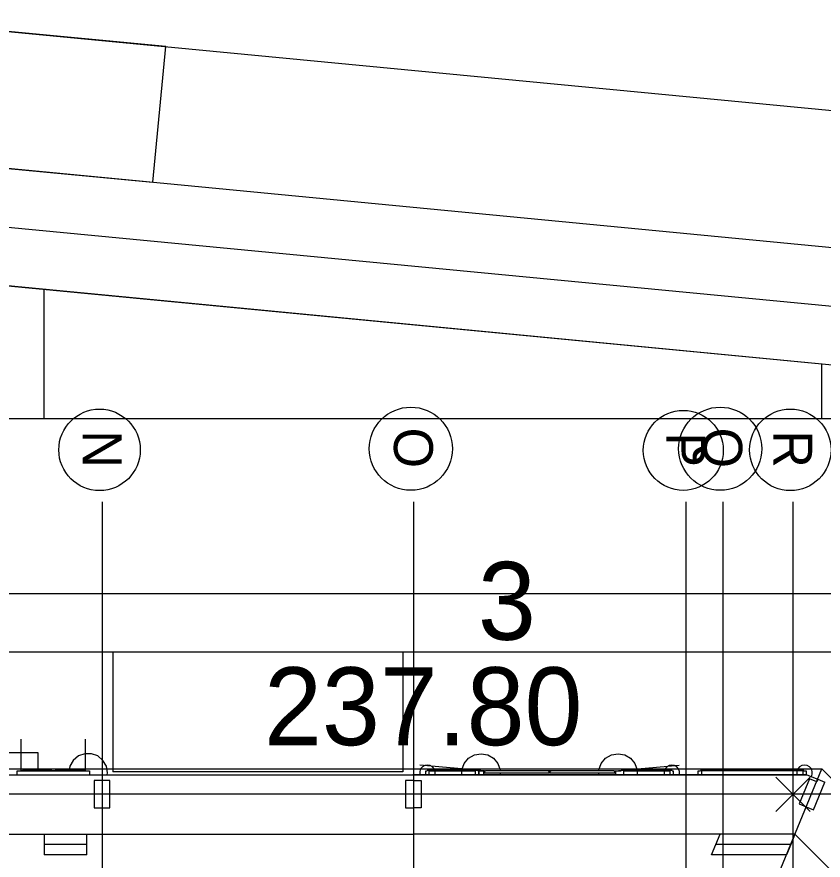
# Model space of a CAD drawing. Extents: x -264165 to -263575, y -1242333 to -1242036.
# Drawn here: x -263829.66 to -263808.94, y -1242089.65 to -1242067.99 of the extents above; entities that cross this region are included whole.
import ezdxf

# ---------------------------------------------------------------- set-up
doc = ezdxf.new("R2010")
doc.units = 0
for name, color, linetype in [('KFA_BODY_VYTYCOVAK', 7, 'Continuous'), ('KFA_HESCON_OSI_STAVBY', 7, 'Continuous'), ('KFA_SITUACIA_DRS_VYTYCOVAK_SEDA', 7, 'Continuous')]:
    doc.layers.add(name, color=color, linetype=linetype)

msp = doc.modelspace()

# ---------------------------------------------------------------- linework, layer by layer
at = {"layer": 'KFA_BODY_VYTYCOVAK'}
for p, q in [((-263810.152, -1242088.402), (-263809.268, -1242087.518)), ((-263809.268, -1242088.402), (-263810.152, -1242087.518))]:
    msp.add_line(p, q, dxfattribs=at)
at = {"layer": 'KFA_HESCON_OSI_STAVBY'}
for p, q in [((-263827.468, -1242080.447), (-263827.468, -1242080.447)), ((-263827.468, -1242080.447), (-263827.468, -1242248.737)), ((-263819.468, -1242080.447), (-263819.468, -1242080.447)), ((-263819.468, -1242080.447), (-263819.468, -1242248.737)), ((-263812.468, -1242080.447), (-263812.468, -1242080.447)), ((-263812.468, -1242080.447), (-263812.468, -1242248.737)), ((-263811.518, -1242080.447), (-263811.518, -1242080.447)), ((-263811.518, -1242080.447), (-263811.518, -1242248.737)), ((-263809.718, -1242080.447), (-263809.718, -1242080.447)), ((-263809.718, -1242080.447), (-263809.718, -1242248.737)), ((-263818.92, -1242111.335), (-263808.968, -1242087.307)), ((-263787.486, -1242087.957), (-263921.823, -1242087.957))]:
    msp.add_line(p, q, dxfattribs=at)
for centre, radius in [((-263827.533, -1242079.111), 1.047), ((-263819.533, -1242079.082), 1.068), ((-263812.533, -1242079.124), 1.027), ((-263811.583, -1242079.082), 1.068), ((-263809.783, -1242079.111), 1.047)]:
    msp.add_circle(centre, radius, dxfattribs=at)
at = {"layer": 'KFA_SITUACIA_DRS_VYTYCOVAK_SEDA'}
for p, q in [((-263765.318, -1242074.565), (-263863.949, -1242065.106)), ((-263825.827, -1242068.753), (-263832.746, -1242068.099)), ((-263765.364, -1242078.076), (-263864.283, -1242068.59)), ((-263826.161, -1242072.237), (-263825.827, -1242068.753)), ((-263766.58, -1242079.467), (-263864.426, -1242070.084)), ((-263765.366, -1242081.09), (-263864.57, -1242071.577)), ((-263766.58, -1242080.973), (-263864.546, -1242071.579)), ((-263833.106, -1242071.58), (-263826.161, -1242072.237)), ((-263828.968, -1242074.991), (-263828.968, -1242078.308)), ((-263808.968, -1242076.909), (-263828.968, -1242074.991)), ((-263808.968, -1242076.909), (-263828.968, -1242074.991)), ((-263828.968, -1242074.991), (-263828.968, -1242078.308)), ((-263808.968, -1242078.308), (-263808.968, -1242076.909)), ((-263808.968, -1242078.308), (-263808.968, -1242076.909)), ((-263918.093, -1242078.308), (-263807.725, -1242078.308)), ((-263828.968, -1242078.308), (-263808.968, -1242078.308)), ((-263828.968, -1242078.308), (-263823.968, -1242078.308)), ((-263823.968, -1242078.308), (-263808.968, -1242078.308)), ((-263808.225, -1242082.808), (-263916.593, -1242082.808)), ((-263807.725, -1242084.308), (-263851.968, -1242084.308)), ((-263827.188, -1242084.307), (-263827.188, -1242087.377)), ((-263827.188, -1242084.307), (-263827.188, -1242087.377)), ((-263819.738, -1242084.307), (-263827.188, -1242084.307)), ((-263819.738, -1242084.307), (-263827.188, -1242084.307)), ((-263819.738, -1242084.307), (-263819.738, -1242087.377)), ((-263819.738, -1242084.307), (-263819.738, -1242087.377)), ((-263829.543, -1242087.357), (-263829.543, -1242086.542)), ((-263829.543, -1242087.357), (-263829.543, -1242086.542)), ((-263827.893, -1242087.357), (-263827.893, -1242086.542)), ((-263827.893, -1242087.357), (-263827.893, -1242086.542)), ((-263829.108, -1242086.896), (-263832.828, -1242086.896)), ((-263829.108, -1242086.896), (-263832.828, -1242086.896)), ((-263829.108, -1242087.347), (-263829.108, -1242086.896)), ((-263829.108, -1242087.347), (-263829.108, -1242086.896)), ((-263828.078, -1242086.974), (-263828.211, -1242087.086)), ((-263828.078, -1242086.974), (-263828.211, -1242087.086)), ((-263827.915, -1242086.915), (-263828.078, -1242086.974)), ((-263827.915, -1242086.915), (-263828.078, -1242086.974)), ((-263827.741, -1242086.915), (-263827.915, -1242086.915)), ((-263827.741, -1242086.915), (-263827.915, -1242086.915)), ((-263827.578, -1242086.974), (-263827.741, -1242086.915)), ((-263827.578, -1242086.974), (-263827.741, -1242086.915)), ((-263827.445, -1242087.086), (-263827.578, -1242086.974)), ((-263827.445, -1242087.086), (-263827.578, -1242086.974)), ((-263818.049, -1242087.034), (-263817.899, -1242086.947)), ((-263818.049, -1242087.034), (-263817.899, -1242086.947)), ((-263817.899, -1242086.947), (-263817.728, -1242086.917)), ((-263817.899, -1242086.947), (-263817.728, -1242086.917)), ((-263817.728, -1242086.917), (-263817.557, -1242086.947)), ((-263817.728, -1242086.917), (-263817.557, -1242086.947)), ((-263817.557, -1242086.947), (-263817.406, -1242087.034)), ((-263817.557, -1242086.947), (-263817.406, -1242087.034)), ((-263814.529, -1242087.034), (-263814.379, -1242086.947)), ((-263814.529, -1242087.034), (-263814.379, -1242086.947)), ((-263814.379, -1242086.947), (-263814.208, -1242086.917)), ((-263814.379, -1242086.947), (-263814.208, -1242086.917)), ((-263814.208, -1242086.917), (-263814.037, -1242086.947)), ((-263814.208, -1242086.917), (-263814.037, -1242086.947)), ((-263814.037, -1242086.947), (-263813.886, -1242087.034)), ((-263814.037, -1242086.947), (-263813.886, -1242087.034)), ((-263828.211, -1242087.086), (-263828.298, -1242087.236)), ((-263828.211, -1242087.086), (-263828.298, -1242087.236)), ((-263827.358, -1242087.236), (-263827.445, -1242087.086)), ((-263827.358, -1242087.236), (-263827.445, -1242087.086)), ((-263817.643, -1242087.357), (-263819.301, -1242087.212)), ((-263817.643, -1242087.357), (-263819.301, -1242087.212)), ((-263819.108, -1242087.207), (-263819.176, -1242087.219)), ((-263819.108, -1242087.207), (-263819.176, -1242087.219)), ((-263819.039, -1242087.219), (-263819.108, -1242087.207)), ((-263819.039, -1242087.219), (-263819.108, -1242087.207)), ((-263818.22, -1242087.33), (-263818.161, -1242087.167)), ((-263818.22, -1242087.33), (-263818.161, -1242087.167)), ((-263818.161, -1242087.167), (-263818.049, -1242087.034)), ((-263818.161, -1242087.167), (-263818.049, -1242087.034)), ((-263817.406, -1242087.034), (-263817.295, -1242087.167)), ((-263817.406, -1242087.034), (-263817.295, -1242087.167)), ((-263817.295, -1242087.167), (-263817.235, -1242087.33)), ((-263817.295, -1242087.167), (-263817.235, -1242087.33)), ((-263814.7, -1242087.33), (-263814.641, -1242087.167)), ((-263814.7, -1242087.33), (-263814.641, -1242087.167)), ((-263814.641, -1242087.167), (-263814.529, -1242087.034)), ((-263814.641, -1242087.167), (-263814.529, -1242087.034)), ((-263814.293, -1242087.357), (-263812.634, -1242087.212)), ((-263814.293, -1242087.357), (-263812.634, -1242087.212)), ((-263813.886, -1242087.034), (-263813.775, -1242087.167)), ((-263813.886, -1242087.034), (-263813.775, -1242087.167)), ((-263813.775, -1242087.167), (-263813.715, -1242087.33)), ((-263813.775, -1242087.167), (-263813.715, -1242087.33)), ((-263812.828, -1242087.207), (-263812.896, -1242087.219)), ((-263812.828, -1242087.207), (-263812.896, -1242087.219)), ((-263812.759, -1242087.219), (-263812.828, -1242087.207)), ((-263812.759, -1242087.219), (-263812.828, -1242087.207)), ((-263809.414, -1242087.207), (-263809.483, -1242087.219)), ((-263809.414, -1242087.207), (-263809.483, -1242087.219)), ((-263809.346, -1242087.219), (-263809.414, -1242087.207)), ((-263809.346, -1242087.219), (-263809.414, -1242087.207)), ((-263894.968, -1242087.307), (-263808.968, -1242087.307)), ((-263829.648, -1242087.457), (-263829.648, -1242087.357)), ((-263829.648, -1242087.457), (-263829.648, -1242087.357)), ((-263829.648, -1242087.357), (-263827.788, -1242087.357)), ((-263829.648, -1242087.357), (-263827.788, -1242087.357)), ((-263829.517, -1242087.357), (-263829.543, -1242087.357)), ((-263829.517, -1242087.357), (-263829.543, -1242087.357)), ((-263829.517, -1242087.357), (-263829.517, -1242087.347)), ((-263829.517, -1242087.357), (-263829.517, -1242087.347)), ((-263828.758, -1242087.347), (-263829.517, -1242087.347)), ((-263828.758, -1242087.347), (-263829.517, -1242087.347)), ((-263828.758, -1242087.357), (-263828.758, -1242087.347)), ((-263828.758, -1242087.357), (-263828.758, -1242087.347)), ((-263828.758, -1242087.347), (-263828.678, -1242087.347)), ((-263828.758, -1242087.347), (-263828.678, -1242087.347)), ((-263828.758, -1242087.357), (-263828.758, -1242087.347)), ((-263828.758, -1242087.357), (-263828.758, -1242087.347)), ((-263828.728, -1242087.357), (-263828.758, -1242087.357)), ((-263828.728, -1242087.357), (-263828.758, -1242087.357)), ((-263828.677, -1242087.357), (-263828.708, -1242087.357)), ((-263828.677, -1242087.357), (-263828.708, -1242087.357)), ((-263828.678, -1242087.347), (-263828.678, -1242087.357)), ((-263828.678, -1242087.347), (-263828.678, -1242087.357)), ((-263828.677, -1242087.347), (-263828.677, -1242087.357)), ((-263828.677, -1242087.347), (-263828.677, -1242087.357)), ((-263827.918, -1242087.347), (-263828.677, -1242087.347)), ((-263827.918, -1242087.347), (-263828.677, -1242087.347)), ((-263828.298, -1242087.236), (-263828.317, -1242087.347)), ((-263828.298, -1242087.236), (-263828.317, -1242087.347)), ((-263827.918, -1242087.347), (-263827.918, -1242087.357)), ((-263827.918, -1242087.347), (-263827.918, -1242087.357)), ((-263827.893, -1242087.357), (-263827.918, -1242087.357)), ((-263827.893, -1242087.357), (-263827.918, -1242087.357)), ((-263827.788, -1242087.357), (-263827.788, -1242087.457)), ((-263827.788, -1242087.357), (-263827.788, -1242087.457)), ((-263827.328, -1242087.407), (-263827.358, -1242087.236)), ((-263827.328, -1242087.407), (-263827.358, -1242087.236)), ((-263827.337, -1242087.457), (-263827.328, -1242087.407)), ((-263827.337, -1242087.457), (-263827.328, -1242087.407)), ((-263819.738, -1242087.377), (-263827.188, -1242087.377)), ((-263819.738, -1242087.377), (-263827.188, -1242087.377)), ((-263819.281, -1242087.307), (-263819.305, -1242087.372)), ((-263819.281, -1242087.307), (-263819.305, -1242087.372)), ((-263819.305, -1242087.372), (-263819.305, -1242087.442)), ((-263819.305, -1242087.372), (-263819.305, -1242087.442)), ((-263819.236, -1242087.254), (-263819.281, -1242087.307)), ((-263819.236, -1242087.254), (-263819.281, -1242087.307)), ((-263819.176, -1242087.219), (-263819.236, -1242087.254)), ((-263819.176, -1242087.219), (-263819.236, -1242087.254)), ((-263819.148, -1242087.357), (-263819.117, -1242087.357)), ((-263819.148, -1242087.357), (-263819.117, -1242087.357)), ((-263819.148, -1242087.457), (-263819.148, -1242087.357)), ((-263819.148, -1242087.457), (-263819.148, -1242087.357)), ((-263817.808, -1242087.347), (-263819.117, -1242087.347)), ((-263817.808, -1242087.347), (-263819.117, -1242087.347)), ((-263819.117, -1242087.347), (-263819.117, -1242087.357)), ((-263819.117, -1242087.347), (-263819.117, -1242087.357)), ((-263819.068, -1242087.357), (-263817.868, -1242087.357)), ((-263819.068, -1242087.357), (-263817.868, -1242087.357)), ((-263819.068, -1242087.357), (-263819.068, -1242087.457)), ((-263819.068, -1242087.357), (-263819.068, -1242087.457)), ((-263818.979, -1242087.254), (-263819.039, -1242087.219)), ((-263818.979, -1242087.254), (-263819.039, -1242087.219)), ((-263818.935, -1242087.307), (-263818.979, -1242087.254)), ((-263818.935, -1242087.307), (-263818.979, -1242087.254)), ((-263818.92, -1242087.347), (-263818.935, -1242087.307)), ((-263818.92, -1242087.347), (-263818.935, -1242087.307)), ((-263818.911, -1242087.372), (-263818.916, -1242087.357)), ((-263818.911, -1242087.372), (-263818.916, -1242087.357)), ((-263818.911, -1242087.442), (-263818.911, -1242087.372)), ((-263818.911, -1242087.442), (-263818.911, -1242087.372)), ((-263818.22, -1242087.347), (-263818.22, -1242087.33)), ((-263818.22, -1242087.347), (-263818.22, -1242087.33)), ((-263818.22, -1242087.457), (-263818.22, -1242087.357)), ((-263818.22, -1242087.457), (-263818.22, -1242087.357)), ((-263817.868, -1242087.457), (-263817.868, -1242087.357)), ((-263817.868, -1242087.457), (-263817.868, -1242087.357)), ((-263817.808, -1242087.357), (-263817.808, -1242087.347)), ((-263817.808, -1242087.357), (-263817.808, -1242087.347)), ((-263817.808, -1242087.357), (-263817.788, -1242087.357)), ((-263817.808, -1242087.357), (-263817.788, -1242087.357)), ((-263817.788, -1242087.357), (-263817.788, -1242087.457)), ((-263817.788, -1242087.357), (-263817.788, -1242087.457)), ((-263817.788, -1242087.457), (-263817.788, -1242087.357)), ((-263817.788, -1242087.457), (-263817.788, -1242087.357)), ((-263817.788, -1242087.357), (-263817.668, -1242087.357)), ((-263817.788, -1242087.357), (-263817.668, -1242087.357)), ((-263817.668, -1242087.357), (-263817.668, -1242087.457)), ((-263817.668, -1242087.357), (-263817.668, -1242087.457)), ((-263817.643, -1242087.357), (-263817.643, -1242087.417)), ((-263817.643, -1242087.357), (-263817.643, -1242087.417)), ((-263817.643, -1242087.357), (-263817.617, -1242087.357)), ((-263817.643, -1242087.357), (-263817.617, -1242087.357)), ((-263815.978, -1242087.417), (-263817.643, -1242087.417)), ((-263815.978, -1242087.417), (-263817.643, -1242087.417)), ((-263817.617, -1242087.347), (-263817.617, -1242087.357)), ((-263817.617, -1242087.347), (-263817.617, -1242087.357)), ((-263817.617, -1242087.347), (-263816.008, -1242087.347)), ((-263817.617, -1242087.347), (-263816.008, -1242087.347)), ((-263817.235, -1242087.33), (-263817.235, -1242087.347)), ((-263817.235, -1242087.33), (-263817.235, -1242087.347)), ((-263817.235, -1242087.417), (-263817.235, -1242087.457)), ((-263817.235, -1242087.417), (-263817.235, -1242087.457)), ((-263816.008, -1242087.357), (-263816.008, -1242087.347)), ((-263816.008, -1242087.357), (-263816.008, -1242087.347)), ((-263816.008, -1242087.347), (-263815.928, -1242087.347)), ((-263816.008, -1242087.347), (-263815.928, -1242087.347)), ((-263816.008, -1242087.357), (-263816.008, -1242087.347)), ((-263816.008, -1242087.357), (-263816.008, -1242087.347)), ((-263815.928, -1242087.357), (-263816.008, -1242087.357)), ((-263815.928, -1242087.357), (-263816.008, -1242087.357)), ((-263816.008, -1242087.357), (-263815.978, -1242087.357)), ((-263816.008, -1242087.357), (-263815.978, -1242087.357)), ((-263815.978, -1242087.417), (-263815.978, -1242087.357)), ((-263815.978, -1242087.417), (-263815.978, -1242087.357)), ((-263815.958, -1242087.357), (-263815.958, -1242087.417)), ((-263815.958, -1242087.357), (-263815.958, -1242087.417)), ((-263815.958, -1242087.357), (-263815.927, -1242087.357)), ((-263815.958, -1242087.357), (-263815.927, -1242087.357)), ((-263814.293, -1242087.417), (-263815.958, -1242087.417)), ((-263814.293, -1242087.417), (-263815.958, -1242087.417)), ((-263815.928, -1242087.347), (-263815.928, -1242087.357)), ((-263815.928, -1242087.347), (-263815.928, -1242087.357)), ((-263815.927, -1242087.347), (-263815.927, -1242087.357)), ((-263815.927, -1242087.347), (-263815.927, -1242087.357)), ((-263815.927, -1242087.347), (-263814.318, -1242087.347)), ((-263815.927, -1242087.347), (-263814.318, -1242087.347)), ((-263814.7, -1242087.347), (-263814.7, -1242087.33)), ((-263814.7, -1242087.347), (-263814.7, -1242087.33)), ((-263814.7, -1242087.457), (-263814.7, -1242087.417)), ((-263814.7, -1242087.457), (-263814.7, -1242087.417)), ((-263814.318, -1242087.357), (-263814.318, -1242087.347)), ((-263814.318, -1242087.357), (-263814.318, -1242087.347)), ((-263814.318, -1242087.357), (-263814.293, -1242087.357)), ((-263814.318, -1242087.357), (-263814.293, -1242087.357)), ((-263814.293, -1242087.417), (-263814.293, -1242087.357)), ((-263814.293, -1242087.417), (-263814.293, -1242087.357)), ((-263814.268, -1242087.457), (-263814.268, -1242087.357)), ((-263814.268, -1242087.457), (-263814.268, -1242087.357)), ((-263814.268, -1242087.357), (-263814.148, -1242087.357)), ((-263814.268, -1242087.357), (-263814.148, -1242087.357)), ((-263814.148, -1242087.357), (-263814.127, -1242087.357)), ((-263814.148, -1242087.357), (-263814.127, -1242087.357)), ((-263812.818, -1242087.347), (-263814.127, -1242087.347)), ((-263812.818, -1242087.347), (-263814.127, -1242087.347)), ((-263814.127, -1242087.347), (-263814.127, -1242087.357)), ((-263814.127, -1242087.347), (-263814.127, -1242087.357)), ((-263814.068, -1242087.357), (-263812.868, -1242087.357)), ((-263814.068, -1242087.357), (-263812.868, -1242087.357)), ((-263814.068, -1242087.357), (-263814.068, -1242087.457)), ((-263814.068, -1242087.357), (-263814.068, -1242087.457)), ((-263813.715, -1242087.33), (-263813.715, -1242087.347)), ((-263813.715, -1242087.33), (-263813.715, -1242087.347)), ((-263813.715, -1242087.357), (-263813.715, -1242087.457)), ((-263813.715, -1242087.357), (-263813.715, -1242087.457)), ((-263813.019, -1242087.357), (-263813.025, -1242087.372)), ((-263813.019, -1242087.357), (-263813.025, -1242087.372)), ((-263813.025, -1242087.372), (-263813.025, -1242087.442)), ((-263813.025, -1242087.372), (-263813.025, -1242087.442)), ((-263813.001, -1242087.307), (-263813.016, -1242087.347)), ((-263813.001, -1242087.307), (-263813.016, -1242087.347)), ((-263812.956, -1242087.254), (-263813.001, -1242087.307)), ((-263812.956, -1242087.254), (-263813.001, -1242087.307)), ((-263812.896, -1242087.219), (-263812.956, -1242087.254)), ((-263812.896, -1242087.219), (-263812.956, -1242087.254)), ((-263812.868, -1242087.457), (-263812.868, -1242087.357)), ((-263812.868, -1242087.457), (-263812.868, -1242087.357)), ((-263812.818, -1242087.357), (-263812.818, -1242087.347)), ((-263812.818, -1242087.357), (-263812.818, -1242087.347)), ((-263812.818, -1242087.357), (-263812.788, -1242087.357)), ((-263812.818, -1242087.357), (-263812.788, -1242087.357)), ((-263812.788, -1242087.357), (-263812.788, -1242087.457)), ((-263812.788, -1242087.357), (-263812.788, -1242087.457)), ((-263812.699, -1242087.254), (-263812.759, -1242087.219)), ((-263812.699, -1242087.254), (-263812.759, -1242087.219)), ((-263812.655, -1242087.307), (-263812.699, -1242087.254)), ((-263812.655, -1242087.307), (-263812.699, -1242087.254)), ((-263812.631, -1242087.372), (-263812.655, -1242087.307)), ((-263812.631, -1242087.372), (-263812.655, -1242087.307)), ((-263812.631, -1242087.442), (-263812.631, -1242087.372)), ((-263812.631, -1242087.442), (-263812.631, -1242087.372)), ((-263812.148, -1242087.457), (-263812.148, -1242087.357)), ((-263812.148, -1242087.457), (-263812.148, -1242087.357)), ((-263812.148, -1242087.357), (-263812.091, -1242087.357)), ((-263812.148, -1242087.357), (-263812.091, -1242087.357)), ((-263812.091, -1242087.347), (-263812.091, -1242087.357)), ((-263812.091, -1242087.347), (-263812.091, -1242087.357)), ((-263809.432, -1242087.347), (-263812.091, -1242087.347)), ((-263809.432, -1242087.347), (-263812.091, -1242087.347)), ((-263809.454, -1242087.357), (-263812.068, -1242087.357)), ((-263809.454, -1242087.357), (-263812.068, -1242087.357)), ((-263812.068, -1242087.357), (-263812.068, -1242087.457)), ((-263812.068, -1242087.357), (-263812.068, -1242087.457)), ((-263809.606, -1242087.357), (-263809.611, -1242087.372)), ((-263809.606, -1242087.357), (-263809.611, -1242087.372)), ((-263809.611, -1242087.372), (-263809.611, -1242087.442)), ((-263809.611, -1242087.372), (-263809.611, -1242087.442)), ((-263809.588, -1242087.307), (-263809.602, -1242087.347)), ((-263809.588, -1242087.307), (-263809.602, -1242087.347)), ((-263809.543, -1242087.254), (-263809.588, -1242087.307)), ((-263809.543, -1242087.254), (-263809.588, -1242087.307)), ((-263809.483, -1242087.219), (-263809.543, -1242087.254)), ((-263809.483, -1242087.219), (-263809.543, -1242087.254)), ((-263809.454, -1242087.457), (-263809.454, -1242087.357)), ((-263809.454, -1242087.457), (-263809.454, -1242087.357)), ((-263809.432, -1242087.347), (-263809.432, -1242087.357)), ((-263809.432, -1242087.347), (-263809.432, -1242087.357)), ((-263809.432, -1242087.357), (-263809.374, -1242087.357)), ((-263809.432, -1242087.357), (-263809.374, -1242087.357)), ((-263809.374, -1242087.357), (-263809.374, -1242087.457)), ((-263809.374, -1242087.357), (-263809.374, -1242087.457)), ((-263809.286, -1242087.254), (-263809.346, -1242087.219)), ((-263809.286, -1242087.254), (-263809.346, -1242087.219)), ((-263809.241, -1242087.307), (-263809.286, -1242087.254)), ((-263809.241, -1242087.307), (-263809.286, -1242087.254)), ((-263809.218, -1242087.372), (-263809.241, -1242087.307)), ((-263809.218, -1242087.372), (-263809.241, -1242087.307)), ((-263809.218, -1242087.442), (-263809.218, -1242087.372)), ((-263809.218, -1242087.442), (-263809.218, -1242087.372)), ((-263808.968, -1242087.307), (-263794.893, -1242101.382)), ((-263834.468, -1242087.457), (-263827.468, -1242087.457)), ((-263834.468, -1242087.457), (-263827.468, -1242087.457)), ((-263834.458, -1242087.457), (-263827.478, -1242087.457)), ((-263834.458, -1242087.457), (-263827.478, -1242087.457)), ((-263827.468, -1242087.607), (-263827.668, -1242087.607)), ((-263827.468, -1242087.607), (-263827.668, -1242087.607)), ((-263827.668, -1242087.607), (-263827.668, -1242088.307)), ((-263827.668, -1242087.607), (-263827.668, -1242088.307)), ((-263827.478, -1242087.457), (-263827.458, -1242087.457)), ((-263827.478, -1242087.457), (-263827.458, -1242087.457)), ((-263827.468, -1242087.457), (-263819.468, -1242087.457)), ((-263827.468, -1242087.457), (-263819.468, -1242087.457)), ((-263827.268, -1242087.607), (-263827.468, -1242087.607)), ((-263827.268, -1242087.607), (-263827.468, -1242087.607)), ((-263827.458, -1242087.457), (-263819.478, -1242087.457)), ((-263827.458, -1242087.457), (-263819.478, -1242087.457)), ((-263827.268, -1242088.307), (-263827.268, -1242087.607)), ((-263827.268, -1242088.307), (-263827.268, -1242087.607)), ((-263819.468, -1242087.607), (-263819.668, -1242087.607)), ((-263819.468, -1242087.607), (-263819.668, -1242087.607)), ((-263819.668, -1242087.607), (-263819.668, -1242088.307)), ((-263819.668, -1242087.607), (-263819.668, -1242088.307)), ((-263819.458, -1242087.457), (-263819.478, -1242087.457)), ((-263819.458, -1242087.457), (-263819.478, -1242087.457)), ((-263809.355, -1242087.457), (-263819.468, -1242087.457)), ((-263809.355, -1242087.457), (-263819.468, -1242087.457)), ((-263819.468, -1242087.607), (-263819.268, -1242087.607)), ((-263819.468, -1242087.607), (-263819.268, -1242087.607)), ((-263819.458, -1242087.457), (-263812.478, -1242087.457)), ((-263819.458, -1242087.457), (-263812.478, -1242087.457)), ((-263819.305, -1242087.442), (-263819.299, -1242087.457)), ((-263819.305, -1242087.442), (-263819.299, -1242087.457)), ((-263819.268, -1242087.607), (-263819.268, -1242088.307)), ((-263819.268, -1242087.607), (-263819.268, -1242088.307)), ((-263818.916, -1242087.457), (-263818.911, -1242087.442)), ((-263818.916, -1242087.457), (-263818.911, -1242087.442)), ((-263813.025, -1242087.442), (-263813.019, -1242087.457)), ((-263813.025, -1242087.442), (-263813.019, -1242087.457)), ((-263812.636, -1242087.457), (-263812.631, -1242087.442)), ((-263812.636, -1242087.457), (-263812.631, -1242087.442)), ((-263812.458, -1242087.457), (-263812.478, -1242087.457)), ((-263812.458, -1242087.457), (-263812.478, -1242087.457)), ((-263812.458, -1242087.457), (-263809.355, -1242087.457)), ((-263812.458, -1242087.457), (-263809.355, -1242087.457)), ((-263809.611, -1242087.442), (-263809.606, -1242087.457)), ((-263809.611, -1242087.442), (-263809.606, -1242087.457)), ((-263809.288, -1242087.557), (-263809.556, -1242088.204)), ((-263809.288, -1242087.557), (-263809.556, -1242088.204)), ((-263809.355, -1242087.457), (-263809.077, -1242087.572)), ((-263809.355, -1242087.457), (-263809.077, -1242087.572)), ((-263809.103, -1242087.634), (-263809.288, -1242087.557)), ((-263809.103, -1242087.634), (-263809.288, -1242087.557)), ((-263809.24, -1242087.505), (-263809.218, -1242087.442)), ((-263809.24, -1242087.505), (-263809.218, -1242087.442)), ((-263809.186, -1242088.357), (-263808.893, -1242087.649)), ((-263809.186, -1242088.357), (-263808.893, -1242087.649)), ((-263809.077, -1242087.572), (-263809.103, -1242087.634)), ((-263809.077, -1242087.572), (-263809.103, -1242087.634)), ((-263809.077, -1242087.572), (-263808.893, -1242087.649)), ((-263809.077, -1242087.572), (-263808.893, -1242087.649)), ((-263809.556, -1242088.204), (-263809.371, -1242088.281)), ((-263809.556, -1242088.204), (-263809.371, -1242088.281)), ((-263809.371, -1242088.281), (-263809.186, -1242088.357)), ((-263809.371, -1242088.281), (-263809.186, -1242088.357)), ((-263827.668, -1242088.307), (-263827.468, -1242088.307)), ((-263827.668, -1242088.307), (-263827.468, -1242088.307)), ((-263827.468, -1242088.307), (-263827.268, -1242088.307)), ((-263827.468, -1242088.307), (-263827.268, -1242088.307)), ((-263819.668, -1242088.307), (-263819.468, -1242088.307)), ((-263819.668, -1242088.307), (-263819.468, -1242088.307)), ((-263819.268, -1242088.307), (-263819.468, -1242088.307)), ((-263819.268, -1242088.307), (-263819.468, -1242088.307)), ((-263834.468, -1242088.982), (-263827.468, -1242088.982)), ((-263834.468, -1242088.982), (-263827.468, -1242088.982)), ((-263828.956, -1242088.982), (-263828.956, -1242089.249)), ((-263828.956, -1242088.982), (-263828.956, -1242089.249)), ((-263827.856, -1242089.249), (-263827.856, -1242088.982)), ((-263827.856, -1242089.249), (-263827.856, -1242088.982)), ((-263827.468, -1242088.982), (-263819.468, -1242088.982)), ((-263827.468, -1242088.982), (-263819.468, -1242088.982)), ((-263809.662, -1242088.982), (-263819.468, -1242088.982)), ((-263809.662, -1242088.982), (-263819.468, -1242088.982)), ((-263811.697, -1242089.249), (-263811.587, -1242088.982)), ((-263811.697, -1242089.249), (-263811.587, -1242088.982)), ((-263809.662, -1242088.982), (-263809.772, -1242089.249)), ((-263809.662, -1242088.982), (-263809.772, -1242089.249)), ((-263809.662, -1242088.982), (-263805.59, -1242093.054)), ((-263809.662, -1242088.982), (-263805.59, -1242093.054)), ((-263827.856, -1242089.249), (-263828.956, -1242089.249)), ((-263827.856, -1242089.249), (-263828.956, -1242089.249)), ((-263828.956, -1242089.249), (-263828.956, -1242089.516)), ((-263828.956, -1242089.249), (-263828.956, -1242089.516)), ((-263827.856, -1242089.516), (-263827.856, -1242089.249)), ((-263827.856, -1242089.516), (-263827.856, -1242089.249)), ((-263811.808, -1242089.516), (-263811.697, -1242089.249)), ((-263811.808, -1242089.516), (-263811.697, -1242089.249)), ((-263809.772, -1242089.249), (-263811.697, -1242089.249)), ((-263809.772, -1242089.249), (-263811.697, -1242089.249)), ((-263809.772, -1242089.249), (-263809.883, -1242089.516)), ((-263809.772, -1242089.249), (-263809.883, -1242089.516)), ((-263827.856, -1242089.516), (-263828.956, -1242089.516)), ((-263827.856, -1242089.516), (-263828.956, -1242089.516)), ((-263809.883, -1242089.516), (-263811.808, -1242089.516)), ((-263809.883, -1242089.516), (-263811.808, -1242089.516))]:
    msp.add_line(p, q, dxfattribs=at)

# ---------------------------------------------------------------- texts
at = {"layer": 'KFA_BODY_VYTYCOVAK'}
for s, p in [('3', (-263817.809, -1242083.989)), ('237.80', (-263823.305, -1242086.696))]:
    msp.add_text(s, height=2, dxfattribs=at).set_placement(p)
at = {"layer": 'KFA_HESCON_OSI_STAVBY'}
for s, p in [('N', (-263827.968, -1242078.607)), ('O', (-263819.968, -1242078.539)), ('P', (-263812.968, -1242078.659)), ('Q', (-263812.018, -1242078.539)), ('R', (-263810.218, -1242078.607))]:
    msp.add_text(s, height=1, rotation=270, dxfattribs=at).set_placement(p)

doc.saveas('drawing.dxf')
